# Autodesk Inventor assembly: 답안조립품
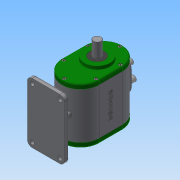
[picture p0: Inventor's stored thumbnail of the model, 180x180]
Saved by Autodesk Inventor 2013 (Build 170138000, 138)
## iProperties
Created: 2018-10
Part Number: 답안조립품
Document SubType Name: Assembly
Designer: Administrator
Author: Administrator
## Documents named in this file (15)
- C:\Users\Administrator\Desktop\381007V1017\답안조립품.iam
- C:\Users\Administrator\Desktop\381007V1017\본체.ipt
- C:\Users\Administrator\Desktop\381007V1017\가변스프링1.ipt
- C:\Users\Administrator\Desktop\381007V1017\가변스프링2.ipt
- C:\Users\Administrator\Desktop\381007V1017\뒤커버.ipt
- C:\Users\Administrator\Desktop\381007V1017\메인축.ipt
- C:\Users\Administrator\Desktop\381007V1017\베어링 608.ipt
- C:\Users\Administrator\Desktop\381007V1017\베어링 6003.ipt
- C:\Users\Administrator\Desktop\381007V1017\볼트 M4.ipt
- C:\Users\Administrator\Desktop\381007V1017\부시.ipt
- C:\Users\Administrator\Desktop\381007V1017\서브축.ipt
- C:\Users\Administrator\Desktop\381007V1017\슬라이더.ipt
- C:\Users\Administrator\Desktop\381007V1017\앞커버.ipt
- C:\Users\Administrator\Desktop\381007V1017\오일실 8 22 7.ipt
- C:\Users\Administrator\Desktop\381007V1017\오일실 17 32 8.ipt
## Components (2 placed, 2 different names)
1. 가변스프링1:1
2. 가변스프링2:1
